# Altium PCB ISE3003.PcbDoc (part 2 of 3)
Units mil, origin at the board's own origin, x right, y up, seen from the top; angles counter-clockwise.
Board outline 3937.01 x 3937.01 mil, 2 copper layers (Top Layer, Bottom Layer), stack 62 mil thick; 230 components, 119 nets, 522 pads, 174 vias.
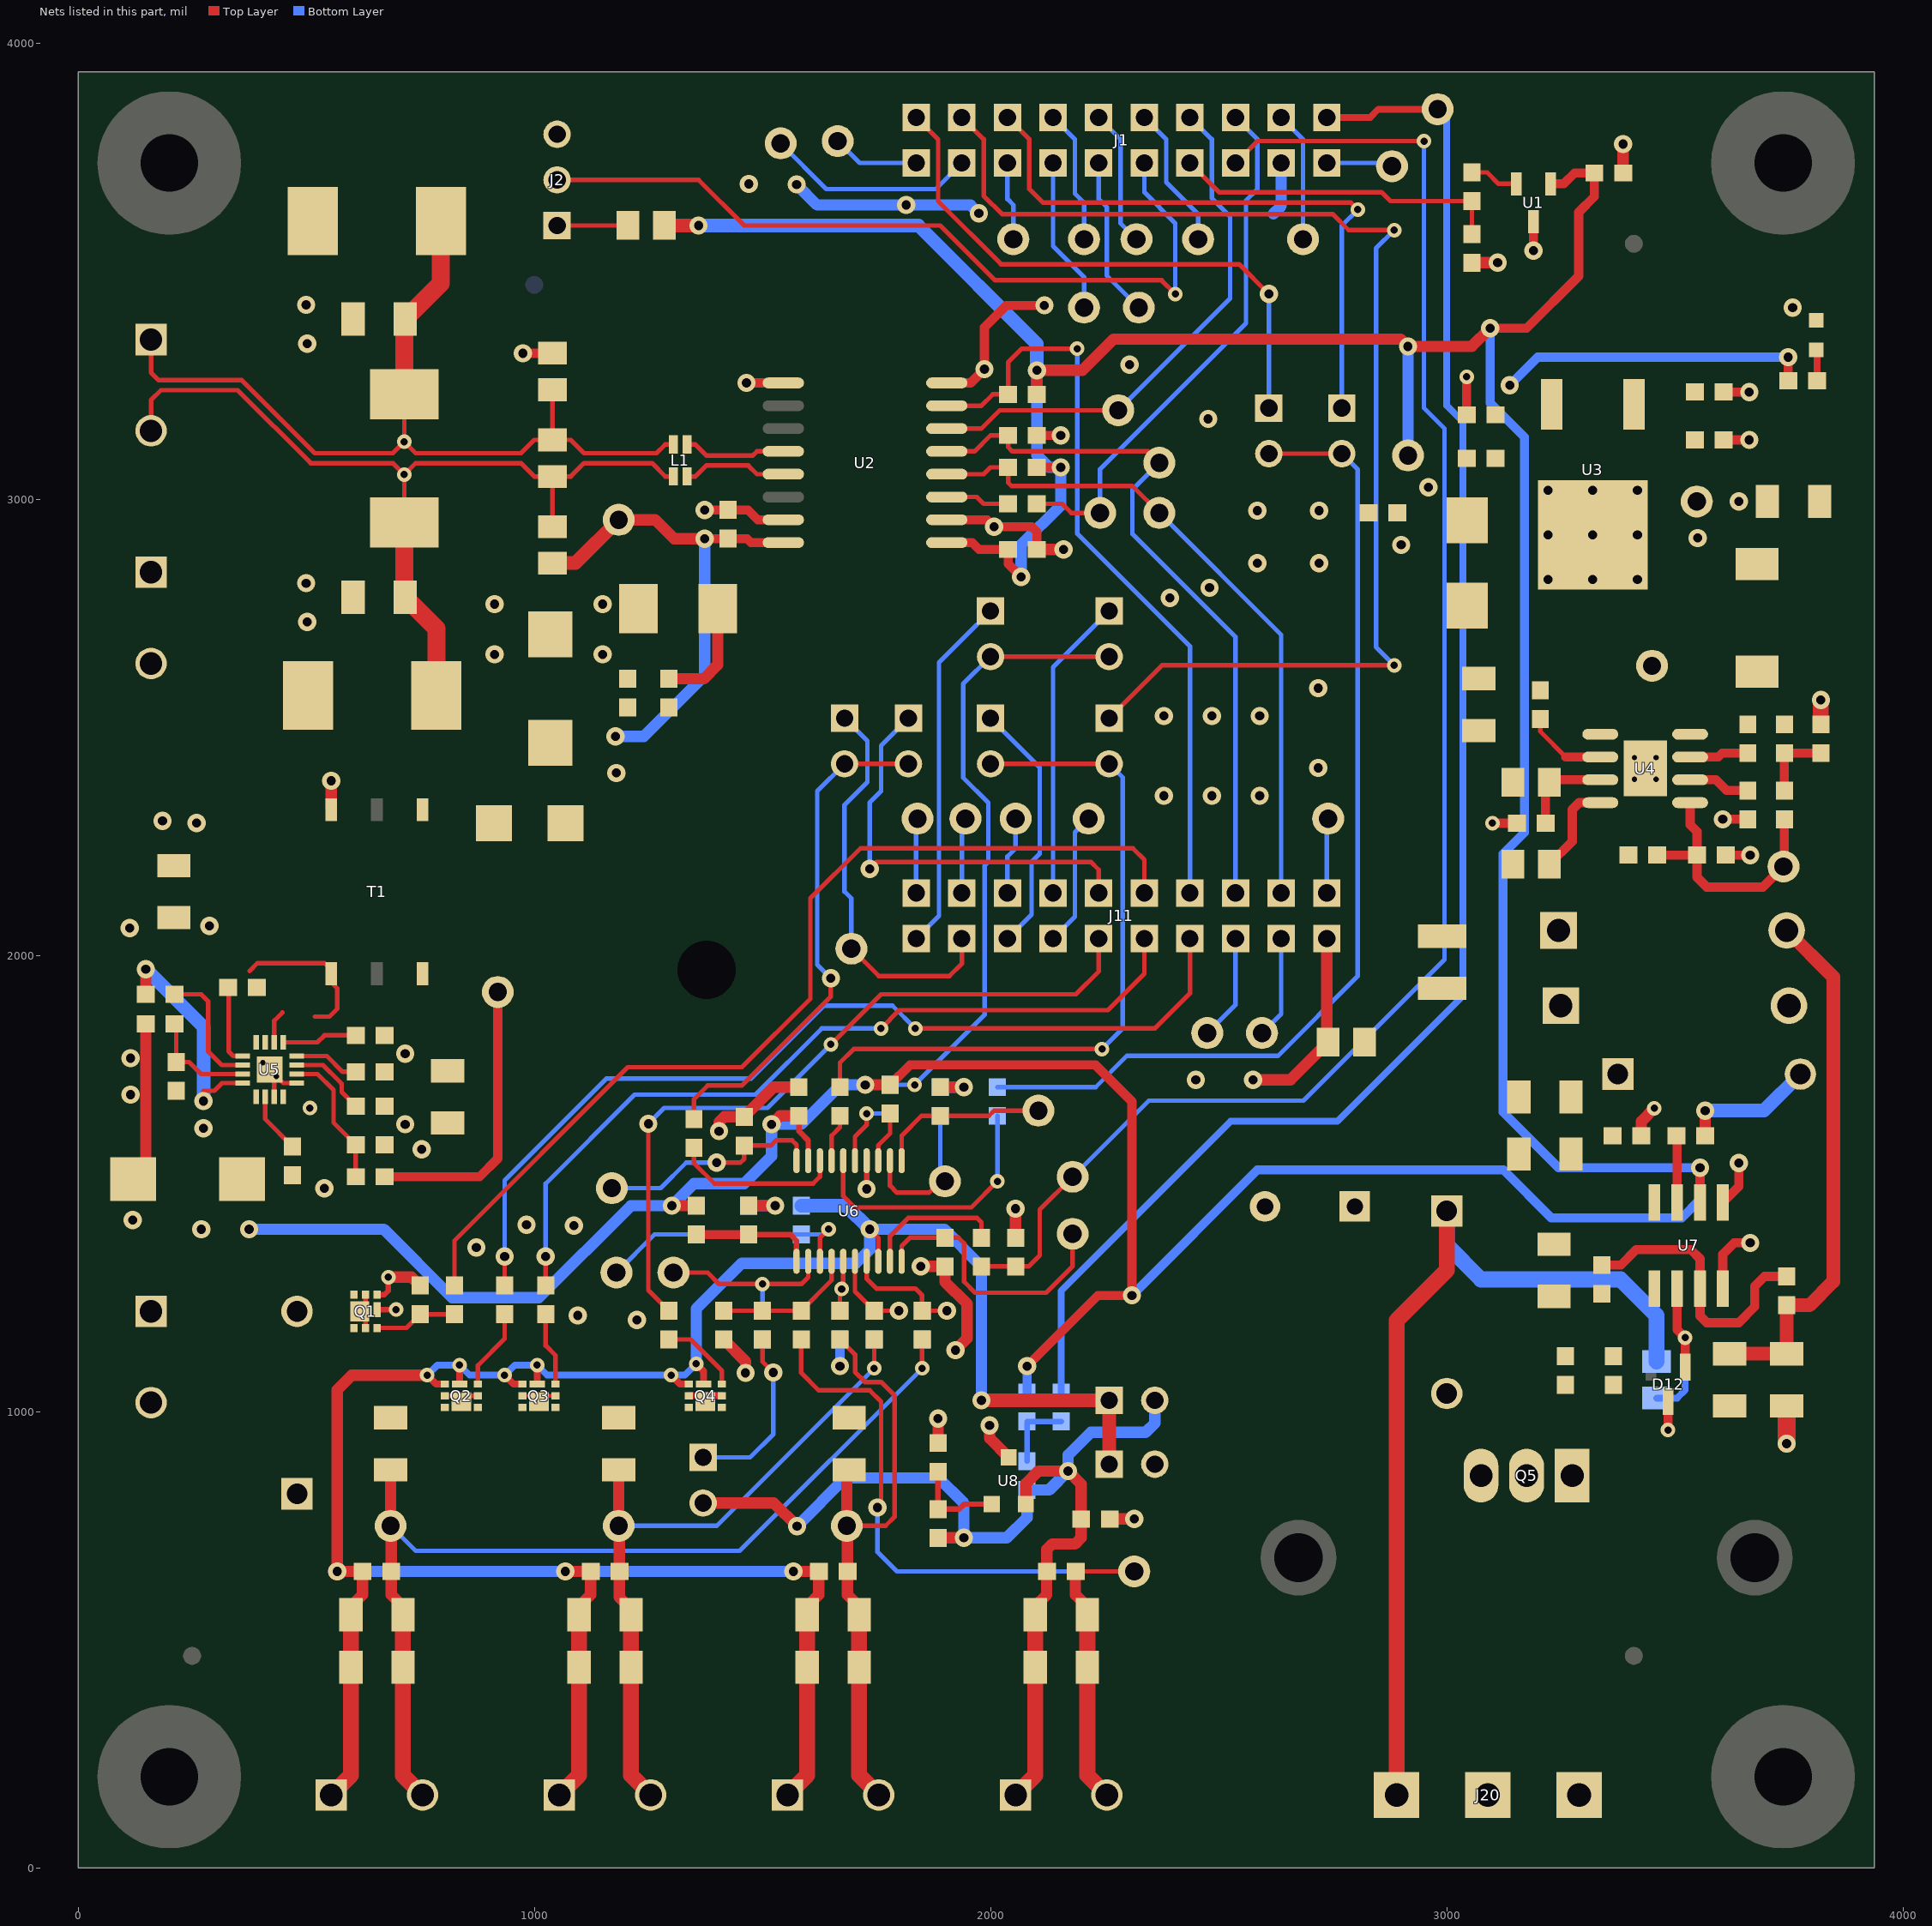
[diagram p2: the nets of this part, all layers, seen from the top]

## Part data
C1 C2 C10 C11 C15 C16 C20 C22 C23 C26 C30 C32 C34 C37 C38: "CAP, CERM, 0.1uF, 25V, +/-5%, X7R, 0603"
C3 C12 C21: "CAP, CERM, 1000pF, 1000V, +/-10%, X7R, 1206"
C4 C7: "CAP, CERM, 1uF, 16V, +/-10%, X7R, 0603"
C5 C8 C29: "CAP, CERM, 0.1uF, 50V, +/-10%, X7R, 0603"
C6: "CAP, TA, 4.7uF, 35V, +/-10%, 1.9 ohm, SMD"
C9: "CAP, CERM, 22uF, 16V, +/-10%, X5R, 1206"
C13 C31: "CAP, TA, 47uF, 35V, +/-10%, 0.3 ohm, SMD"
C14: "CAP, CERM, 1uF, 100V, +/-10%, X7R, 1206"
C17 C27 C33 C35 C36 C43 C44: "CAP, CERM, 0.01uF, 25V, +/-5%, C0G/NP0, 0603"
C18: "CAP, CERM, 3300pF, 50V, +/-10%, X7R, 0603"
C19: "CAP, CERM, 1uF, 25V, +/-10%, X5R, 0603"
C24: "CAP, CERM, 0.1uF, 100V, +/-10%, X7R, 0805"
C25: "CAP, CERM, 22uF, 16V, +/-20%, X5R, 1206"
C28: "CAP, AL, 100uF, 100V, +/-20%, 0.12 ohm, TH"
C39 C40 C41 C42: "CAP, CERM, 100pF, 25V, +/-10%, X7R, 0603"
D1 D3 D5: "Diode, TVS 15V 1500W BIDIR 5% SMC"
D2: "LED SmartLED Green 570NM"
D4: "Diode, Zener, 5.1V, 5W, SMB"
D6: "Diode, Schottky, 20V, 1A, SMA"
D7: "Diode, Zener, 39V, 1W, DO41"
D8: "Diode, Zener, 16V, 1W, DO41"
D9 D10 D11: "Diode, P-N, 1000V, 1A, TH"
D12: "Diode, Switching, 200V, 0.2A, SOT-23"
FB1: library part MMZ1608B102C, "FERRITE CHIP 1000 OHM 300MA 0603"
FID1 FID2 FID3 FID4 FID5 FID6: "Fiducial mark.  There is nothing to buy or mount."
H1 H2 H3 H4: "Machine Screw, Round, #4-40 x 1/4, Nylon, Philips panhead"
H5 H6 H8 H9: "Standoff, Hex, 0.5\"L #4-40 Nylon"
H7: library part "MH 3_0.5MM", "Mountin hole, NPTH Drill 3.2mm"
HS1: "Heatsink, TO-220, Vertical-mount, 5*C/W"
J1 J11: "Header, Male 2x10-pin, 100mil spacing"
J2: "Header, Male 3-pin, 100mil spacing,"
J3 J6 J12 J16 J17 J18 J19: "TERMINAL BLOCK 5.08MM VERT 2POS, TH"
J4 J5 J7 J8 J9 J10 J13 J14 J15 J21 J22: "Header, Male 2-pin, 100mil spacing,"
J20: "Terminal Block, 3-pin, 15-A, 5.1mm"
L1: library part IND_ACM2012_SERIES, "Inductor, Common Mode Filter SMD"
L2: library part IND_SRR7032-221M, "Inductor, 220uH .30A SMD"
L3: library part IND_B82422H1332K, "Inductor, Chip, 3.3uH 770MA 1210 10%"
L4: "1.5A Ferrite Bead, 330 ohm @ 100MHz, SMD"
LBL1: library part THT-14-423-10, "Thermal Transfer Printable Labels, 0.650\" W x 0.200\" H - 10,000 per roll"
Logo1: library part TI_Logo, "Texas Instrument Corporate Signature"
Q1 Q2 Q3 Q4: "MOSFET, N-CH, 30V, 22A, SON 2X2 MM"
Q5: "MOSFET, N-CH, 60V, 50A, TO-220AB"
R1 R33 R41 R68: "RES, 100 ohm, 1%, 0.1W, 0603"
R2: "RES, 1.00k ohm, 1%, 0.125W, 0805"
R3 R10: "RES, 470 ohm, 1%, 0.125W, 0805"
R4 R37 R38 R39 R40: "RES, 300 ohm, 5%, 0.1W, 0603"
R5 R6 R8: "RES, 10k ohm, 5%, 0.1W, 0603"
R7: "RES, 120 ohm, 5%, 0.125W, 0805"
R9: "RES, 10.0 ohm, 1%, 0.1W, 0603"
R11: "RES, 200 ohm, 1%, 0.1W, 0603"
R12: "RES, 63.4k ohm, 1%, 0.1W, 0603"
R13: "RES, 121k ohm, 0.1%, 0.125W, 0805"
R14 R22 R28: "RES, 10.0k ohm, 1%, 0.1W, 0603"
R15: "RES, 1.00k ohm, 1%, 0.1W, 0603"
R16: "RES, 9.76k ohm, 1%, 0.1W, 0603"
R17: "RES, 53.6k ohm, 0.1%, 0.125W, 0805"
R18 R31: "RES, 100k ohm, 1%, 0.1W, 0603"
R19: "RES, 21.5k ohm, 1%, 0.1W, 0603"
R20 R52: "RES, 30k ohm, 5%, 0.1W, 0603"
R21: "RES, 280k ohm, 1%, 0.1W, 0603"
R23 R27 R61 R62: "RES, 10 ohm, 5%, 0.1W, 0603"
R24 R26 R32 R63 R64 R65 R67 R71: "RES, 0 ohm, 5%, 0.1W, 0603"
R25 R29 R34: "RES, 10.0k ohm, 1%, 0.25W, 1206"
R30: "RES, 43.2k ohm, 1%, 0.1W, 0603"
R35: "RES, 1.00Meg ohm, 1%, 0.1W, 0603"
R36 R51: "RES, 10k ohm, 0.01%, 0.063W, 0603"
R42 R43 R44 R70: "RES, 1.0k ohm, 5%, 0.1W, 0603"
R45 R46: "RES, 1.00k ohm, 1%, 0.25W, 1206"
R47: "RES, 510 ohm, 0.1%, 0.1W, 0603"
R48 R49 R50 R53 R54 R55 R56 R57 R58 R59 R60: "RES, 22 ohm, 5%, 0.25W, 1206"
R66: "RES, 47k ohm, 5%, 0.125W, 0805"
R69: "RES, 470 ohm, 5%, 0.1W, 0603"
T1: library part "TRNSFMR 760390015", "Transformer 475uH SMD"
TP1 TP2 TP3 TP4 TP5 TP6 TP7 TP8 TP9 TP10 TP11 TP12 TP13 TP14 TP15 TP16 TP17 TP18 TP19 TP20 TP21 TP22 TP23 TP24 TP25 TP26 TP27 TP28 TP29 TP30 TP31 TP32 TP33 TP34 TP35 TP36 TP37 TP38 TP39 TP40: "Test Point, O.040 Hole"
U1: "2.7V, 15.6mV/°C, Temperature Sensor, 3-pin SOT-23"
U2: "IC, ISOLATED RS-485 PROFIBUS TRANSCEIVER"
U3: "IC, 300-mA 40-V LOW-DROPOUT REGULATOR WITH 25-uA QUIESCENT CURRENT"
U4: "100V, 600mA Constant On-Time Synchronous Buck Regulator, DDA0008B"
U5: "IC, DC-DC Converter"
U6: "ZerØ-Drift Programmable Gain Amplifier with MUX"
U7: "IC, Dual Differential Comparators, 2-36 Vin"
U8: "IC, Micropower Shunt Voltage Reference 100 ppm/°C, 45µA-12mA,  Adjustable"
ZZ1: library part AssemblyNoteLabel
ZZ2 ZZ3 ZZ4: library part AssemblyNote

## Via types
v1: diameter 40, hole 20, Top Layer to Bottom Layer, tented both sides, 134 vias
v2: diameter 32, hole 16, Top Layer to Bottom Layer, tented both sides, 34 vias
v3: diameter 26, hole 12, Top Layer to Bottom Layer, tented both sides, 6 vias

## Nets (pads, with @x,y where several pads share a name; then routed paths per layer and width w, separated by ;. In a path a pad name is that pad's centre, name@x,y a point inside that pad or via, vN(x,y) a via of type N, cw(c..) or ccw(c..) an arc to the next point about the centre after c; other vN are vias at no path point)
3.3_REF: J1.1 R67.1 TP1.1 | length 3588.3
  Top Layer w15: J1.1@2737.01,3837.01 2832.01,3837.01 2850,3855 TP1.1@2980,3855
  Bottom Layer w15: R67.1@2155,1041.5 2155,1265 2526.5,1636.5 2760.5,1636.5 3035,1911 3035,3170 3000,3205 3000,3835 TP1.1@2980,3855
12V: C5.1 C7.1 C9.1 C18.1 D9.2 D11.1 J12.2 L2.2 R16.2 R28.2 TP15.1 U3.1 | length 403.6
  Top Layer w20: R16.2@3611.5,2220 v1(3665,2220)
  Top Layer w25: R28.2@3566.5,1605 v1(3566.5,1660)
  Top Layer w35: C18.1@3820,2506.5 v1(3820,2560)
  Bottom Layer w30: v1(3566.5,1660) 3695,1660 D9.2@3775,1740
  other v1: 3550,2915 3640,2995
16V_C: C29.1 D8.1 D9.1 R25.1 R29.1 R34.1 U7.8
39V: C24.1 C28.1 D7.1 D10.1 J20.1 L3.1 R25.2 R29.2 R66.2 | length 2027.4
  Top Layer w35: J20.1@2890,158 J20.1@2890,160 2890,1200 3000,1310 D10.1@3000,1440
  Bottom Layer w35: D10.1@3000,1440 3000,1365 3075,1290 3381,1290 3460,1211 R66.2@3460,1110
\CS: J21.2 J22.2 R27.2 | length 1124
  Top Layer w10: R27.2@1350,1641.5 1350,1685 1380,1715 1455,1715 1650,1910 v1(1650,1950) ; J22.2@1680,2420 J21.2@1820,2420
  Bottom Layer w10: v1(1650,1950) 1620,1980 1620,2360 J22.2@1680,2420
\CS_M: J11.11 J21.1 | length 931.5
  Top Layer w10: v1(1735,2190) 1750,2205 2220,2205 2237.01,2187.99 J11.11@2237.01,2137.01
  Bottom Layer w10: v1(1735,2190) 1735,2335 1760,2360 1760,2460 J21.1@1820,2520
\CS_T: J11.18 J22.1 TP26.1 | length 885.7
  Top Layer w10: TP26.1@1695,2015 1755,1955 1910,1955 1937.01,1982.01 J11.18@1937.01,2037.01
  Bottom Layer w10: J22.1@1680,2520 1730,2470 1730,2380 1680,2330 1680,2140 1695,2125 TP26.1@1695,2015
AVDD: C32.2 L4.1 U6.1 | length 270.8
  Top Layer w12: C32.2@1470,1388.5 1561.5,1388.5 1574.84,1375.16 U6.1@1574.84,1329.76
  Top Layer w20: L4.1@1355,1388.5 C32.2@1470,1388.5
B_G: J11.12 R40.1 | length 1625.5
  Top Layer w10: v1(1250,1631) 1250,1266.5 R40.1@1295,1221.5 ; v2(1650,1805) 1760,1915 2187.01,1915 2237.01,1965 J11.12@2237.01,2037.01
  Bottom Layer w10: v1(1250,1631) 1285,1666 1511,1666 v2(1650,1805)
B_IP: C41.1 J18.2 R50.1 R55.2 R59.2 R70.1 TP33.1 | length 1334.9
  Top Layer w10: R70.1@1670,1158.5 1703,1125.5 1703,1087 1725,1065 1760,1065 1790,1035 1790,770 1770,750 TP33.1@1685,750
  Top Layer w25: R50.1@1680,882.91 1685,877.91 TP33.1@1685,750 ; TP33.1@1686.5,748.5 C41.1@1686.5,650 1686.5,598.5 1712.09,572.91 R55.2@1712.09,555
  Top Layer w35: R55.2@1712.09,555 R59.2@1712.09,440 1712.09,202.91 J18.2@1755,160
  Bottom Layer w10: TP33.1@1677.2,757.8 TP33.1@1685,750
C5V: C10.2 C13.1 C15.1 D6.1 R10.2 R11.2 TP18.1 U2.16 | length 1116.7
  Top Layer w20: v1(1373.5,2913.5) C10.2@1425,2913.5 1466.5,2913.5 1475,2905 U2.16@1545.87,2905
  Top Layer w25: TP18.1@1185,2955 1265,2955 1306.5,2913.5 v1(1373.5,2913.5)
  Top Layer w30: R10.2@1040,2860 1090,2860 TP18.1@1185,2955
  Bottom Layer w25: v1(1178,2480) 1240,2480 1373.5,2613.5 v1(1373.5,2913.5)
  other v1: 1180,2400
EGND: C3.2 C12.1 D1.1 D5.2 J6.2
  other v1: 502.5,2731 500,2816 502.5,3341 500,3426
FSD: J11.9 R37.1 | length 2179
  Top Layer w10: R37.1@825,1276.5 825,1375 1205,1755 1455.06,1755 1605.06,1905 1605.06,2125.06 1715,2235 2312.01,2235 2337.01,2210 J11.9@2337.01,2137.01
GND: C1.2 C2.1 C4.2 C5.2 C6.2 C7.2 C8.2 C9.2 C11.1 C14.1 C16.2 C19.2 C21.2 C23.1 C24.2 C25.2 C26.1 C27.2 C28.2 C29.2 C30.2 C31.2 C32.1 C33.2 C34.2 C35.2 C36.2 C38.1 C43.2 C44.2 D2.1 D8.2 D12.3 J1.4 J2.3 J11.2 J15.2 J20.2 Q1.4 Q1.7 Q5.3 R6.1 R14.1 R15.1 R19.1 R21.1 R24.1 R26.1 R30.1 R32.1 R45.1 R46.1 R51.1 R63.1 R64.1 R65.1 U1.3 U2.2 U2.8 U3.2 U4.1 U4.9 U5.3 U5.4 U5.5 U5.17 U6.14 U7.4 U7.5 U8.3 | length 4458.4
  Top Layer w10: U5.17@420.05,1750.15 U5.17@429.85,1740.35 ; U5.3@429.85,1680.15 U5.3@429.85,1690.55 U5.17@429.85,1740.35 ; U5.5@479.5,1720.5 449.7,1720.5 U5.17@429.85,1740.35
  Top Layer w12: Q1.7@655.59,1223.78 v2(697.2,1223.78) ; Q1.4@655.59,1256.32 671.32,1256.32 680,1265 v2(680,1295) ; v1(1728.39,1488.39) U6.14@1728.39,1550.24
  Top Layer w20: U2.2@1904.13,2955 1993,2955 v1(2008,2940) 2090,2940 2101.5,2928.5 C11.1@2101.5,2890 ; U2.8@1904.13,3255 1956.64,3255 v1(1986.64,3285) 1986.64,3376.64 2035,3425 v1(2118,3425) ; R6.1@2101.5,3140 v1(2154,3140) ; C4.2@3043.5,3185 v2(3043.5,3268.5) ; v2(3100,2290) R14.1@3148.5,2290 ; v1(3190,3545) U1.3@3190,3608.66 ; v2(3485,960) D12.3@3485,1022.6 ; U7.4@3605,1270 3605,1345 3630,1370 v1(3665,1370) ; U7.5@3605,1459 3640,1494 v1(3640,1545) ; v1(3605,2298.5) C19.2@3660,2298.5 ; C7.2@3606.5,3130 v1(3663,3130) ; C5.2@3606.5,3235 v1(3663,3235)
  Top Layer w25: C31.2@120.91,1510 148.5,1537.6 R19.1@148.5,1850 ; v2(680,1295) 730.45,1295 748.96,1276.5 C34.2@750,1276.5 ; v1(1405,1615) 1405,1635 1416.5,1646.5 R26.1@1460,1646.5 1525,1711.5 C26.1@1580,1711.5 ; C35.2@1415,1158.5 1463,1110.5 v1(1463,1085) ; C32.1@1470,1451.5 v1(1528,1451.5) ; v1(1847.16,1318.5) R32.1@1900,1318.5 1900,1285 1948.5,1236.5 1948.5,1160.5 v1(1923,1135) ; R51.1@1885,931.5 v1(1885,985) ; R24.1@1890,1711.5 v1(1941.5,1711.5) ; v1(1998,970) 1998,942 U8.3@2040,900 ; C33.2@2055,1381.5 v1(2055,1445) ; C11.1@2101.5,2890 v1(2160,2890) ; C38.1@2261.5,765 v1(2315,765) ; v1(2575.5,1727.5) 2657.5,1727.5 C24.2@2740,1810 2737.01,1812.99 J11.2@2737.01,2037.01 ; C2.1@3055,3518.5 v1(3111.5,3518.5) ; C1.2@3386.5,3715 v1(3386.5,3778.5) ; C29.2@3426.5,1605 3426.5,1636.5 v2(3455,1665)
  Top Layer w40: v1(3745,930) R46.1@3745,1012.91
  Bottom Layer w20: v1(1670,1100) C36.2@1670,1158.5
  Bottom Layer w25: R64.1@1470,1451.5 v1(1528,1451.5) ; v1(1575,3690) 1620,3645 v1(1815,3645) 1956,3645 v1(1974.5,3626.5) ; R63.1@1890,1711.5 v1(1941.5,1711.5) ; 2620,3626 2637.01,3643.01 J1.4@2637.01,3737.01
  other v1: 1225,1201 1095,1211 873,1360 1087,1408 983,1410 120,1420 539.95,1489.85 753,1575 717,1630 115,1695 2450,1727.5 115,1775 717,1785 113,2060 288,2065 2380,2350 2485,2350 2590,2350 2718.01,2411 2380,2525 2485,2525 2590,2525 2718.01,2586 2393,2784 2480,2806 3222,2823.89 3320,2823.89 3418,2823.89 2585,2860 2720,2860 3222,2921.89 3320,2921.89 3418,2921.89 2585,2975 2720,2975 3222,3019.89 3320,3019.89 3418,3019.89 2477,3176 2305,3295 3758,3420 1470,3691
  other v2: 507.95,1665.85
  other v3: 434.95,1734.85 404.95,1764.85 3411.38,2386.38 3458.62,2386.38 3411.38,2433.62 3458.62,2433.62
N_IP: C42.1 J19.2 R42.1 R56.2 R60.2 TP34.1 | length 1842.5
  Top Layer w10: R42.1@1585,1158.5 1585,1085 1623,1047 1735,1047 1760,1022 1760,798 v1(1752,790) ; C42.1@2186.5,650 TP34.1@2315,650
  Top Layer w25: C42.1@2185.99,650 2185.99,598.5 2211.58,572.91 R56.2@2211.58,555
  Top Layer w35: R56.2@2212.09,562.91 R56.2@2212.09,555 R60.2@2212.09,440 2212.09,202.91 J19.2@2255,160
  Bottom Layer w10: v1(1752,790) 1752,693 1795,650 TP34.1@2315,650
NetC4_1: C4.1 FB1.1 R4.2 U3.3 | length 687.5
  Top Layer w20: R4.2@3748.5,3260 v1(3748.5,3311.5)
  Bottom Layer w20: v1(3138,3250) 3199.5,3311.5 v1(3748.5,3311.5)
NetC14_2: C14.2 C16.1 L3.2 R13.2 R17.2 U4.2 | length 182.3
  Top Layer w10: C16.1@3205,2518.5 3205,2491 3261,2435
  Top Layer w20: 3261,2435 U4.2@3336.57,2435
NetC17_1: C17.1 U4.7 | length 130.1
  Top Layer w20: U4.7@3533.43,2435 3595,2435 3603.5,2443.5 C17.1@3660,2443.5
NetC17_2: C17.2 L2.1 R12.1 TP19.1 U4.8
NetC18_2: C18.2 C20.2 R12.2 | length 162
  Top Layer w20: C20.2@3740,2361.5 R12.2@3740,2443.5 C18.2@3820,2443.5
NetC19_1: C19.1 U4.6 | length 136.3
  Top Layer w20: U4.6@3533.43,2385 3590,2385 3613.5,2361.5 C19.1@3660,2361.5
NetC20_1: C20.1 R15.2 R16.1 TP25.1 U4.5 | length 578.1
  Top Layer w20: R15.2@3461.5,2220 R16.1@3548.5,2220 ; U4.5@3533.43,2335 3533.43,2286.57 3548.5,2271.5 R16.1@3548.5,2220 ; C20.1@3740,2298.5 3740,2197 TP25.1@3738,2195 3693,2150 3570,2150 3548.5,2171.5 R16.1@3548.5,2220
NetC22_1: C22.1 T1.1 U5.10 U5.11 U5.12 | length 411.6
  Top Layer w10: 376,1966 393,1983 540,1983 555,1968 T1.1@555,1960 555,1940.95 568,1927.95 568,1882.9 551.1,1866 519.15,1866 ; U5.10@429.85,1809.55 429.85,1856.85 448,1875
NetC22_2: C22.2 U5.13 | length 175.4
  Top Layer w10: C22.2@328.5,1930 330,1928.5 330,1790 340.4,1779.6 U5.13@360.5,1779.6
NetC23_2: C23.2 U5.9 | length 165.4
  Top Layer w10: U5.9@449.55,1809.55 524.55,1809.55 540,1825 C23.2@608.5,1825
NetC25_1: C25.1 R31.1 T1.3 TP27.1 | length 630.1
  Top Layer w20: R31.1@671.5,1515 880,1515 920,1555 TP27.1@920,1920
NetC27_1: C27.1 U5.7 | length 176.9
  Top Layer w10: U5.7@479.5,1759.9 536.83,1759.9 571.73,1725 578,1718.72 578,1700.5 C27.1@608.5,1670
NetC34_1: C34.1 Q1.3 R37.2 | length 181.8
  Top Layer w10: Q1.3@655.59,1183.68 720.18,1183.68 C34.1@750,1213.5 R37.2@825,1213.5
NetC35_1: C35.1 R41.1 R42.2 U6.4 | length 305.9
  Top Layer w10: C35.1@1415,1221.5 R41.1@1500,1221.5 R42.2@1585,1221.5 1651.61,1288.11 U6.4@1651.61,1329.76
NetC36_1: C36.1 R70.2 U6.5 | length 160.5
  Top Layer w10: R70.2@1670,1221.5 1670,1266 1677.2,1273.2 U6.5@1677.2,1329.76
  Bottom Layer w10: C36.1@1670,1221.5 1670,1265.48 v2(1673.7,1269.18)
NetC37_1: C37.1 R34.2 R35.2 R47.1 U7.1
NetC37_2: C37.2 Q5.1 R47.2
NetC43_1: C43.1 R44.2 U6.7 | length 317
  Top Layer w10: U6.7@1728.39,1329.76 1728.39,1291.61 1750,1270 1835,1270 1850,1255 R44.2@1850,1221.5 v1(1904.3,1221.5)
  Bottom Layer w10: C43.1@1850,1221.5 v1(1904.3,1221.5)
NetC44_1: C44.1 R43.2 U6.6 | length 234.3
  Top Layer w10: U6.6@1702.8,1329.76 1702.8,1263.7 R43.2@1745,1221.5 v1(1799.3,1221.5)
  Bottom Layer w10: C44.1@1745,1221.5 v1(1799.3,1221.5)
NetD2_2: D2.2 R4.1 | length 66
  Top Layer w15: R4.1@3811.5,3260 D2.2@3811.5,3326.02
NetD4_1: D4.1 R11.1 | length 242.6
  Top Layer w25: R11.1@1295,2606.5 1371.5,2606.5 1402.01,2637.01 D4.1@1402.01,2760
NetD6_2: D6.2 T1.4
NetD7_2: D7.2 R36.2 R45.2 R46.2 | length 1166.7
  Top Layer w30: R45.2@3620,1127.09 R46.2@3745,1127.09 R36.2@3745,1233.5 3795,1233.5 3847.01,1285.51 3847.01,1952.99 D7.2@3745,2055
NetD10_2: D10.2 J20.3 Q5.2
NetD11_2: D11.2 J12.1 Q1.1 Q1.2 Q1.5 Q1.6 Q1.8 | length 72.6
  Top Layer w10: Q1.2@630,1183.68 Q1.5@630,1256.32
NetD12_1: D12.1 R66.1 U7.2 | length 364.6
  Top Layer w20: U7.2@3505,1270 3505,1180 v2(3522.4,1162.6) D12.1@3522.4,1097.4
  Bottom Layer w15: R66.1@3460,1030 3505,1030 3522.4,1047.4 v2(3522.4,1162.6)
NetJ1_2: J1.2 TP4.1 | length 145.9
  Bottom Layer w10: J1.2@2737.01,3737.01 2872.99,3737.01 TP4.1@2880,3730
NetJ1_3: J1.3 TP9.1 | length 286.9
  Bottom Layer w10: J1.3@2637.01,3837.01 2685,3789.02 TP9.1@2685,3570
NetJ1_9: J1.9 TP8.1 | length 315.9
  Bottom Layer w10: J1.9@2337.01,3837.01 2385,3789.02 2385,3695 2455,3625 TP8.1@2455,3570
NetJ1_11: J1.11 TP7.1 | length 301.4
  Bottom Layer w10: J1.11@2237.01,3837.01 2285,3789.02 2285,3605 TP7.1@2320,3570
NetJ1_12: J1.12 TP11.1 | length 353.5
  Bottom Layer w10: J1.12@2237.01,3737.01 2237.01,3657.99 2255,3640 2255,3490 TP11.1@2325,3420
NetJ1_13: J1.13 TP6.1 | length 295.2
  Bottom Layer w10: J1.13@2137.01,3837.01 2185,3789.02 2185,3670 2205,3650 TP6.1@2205,3570
NetJ1_14: J1.14 TP10.1 | length 345.2
  Bottom Layer w10: J1.14@2137.01,3737.01 2137.01,3555 2205,3487.01 TP10.1@2205,3420
NetJ1_16: J1.16 TP5.1 | length 172.4
  Bottom Layer w10: J1.16@2037.01,3737.01 2037.01,3657.99 2050,3645 TP5.1@2050,3570
NetJ1_18: J1.18 TP3.1 | length 462
  Bottom Layer w10: TP3.1@1540,3780 1640,3680 1880,3680 J1.18@1937.01,3737.01
NetJ1_20: J1.20 TP2.1 | length 191.9
  Bottom Layer w10: TP2.1@1665,3785 1712.99,3737.01 J1.20@1837.01,3737.01
NetJ2_1: J2.1 R2.1 | length 155
  Top Layer w10: J2.1@1050,3600 R2.1@1205,3600
NetJ11_1: J11.1 TP24.1 | length 164.2
  Bottom Layer w10: J11.1@2737.01,2137.01 2737.01,2297.01 TP24.1@2740,2300
NetJ11_4: J11.4 TP29.1 | length 224.4
  Bottom Layer w10: TP29.1@2595,1830 2637.01,1872.01 J11.4@2637.01,2037.01
NetJ11_6: J11.6 TP28.1 | length 232.7
  Bottom Layer w10: TP28.1@2475,1830 2537.01,1892.01 J11.6@2537.01,2037.01
NetJ11_14: J11.14 TP23.1 | length 295.3
  Bottom Layer w10: J11.14@2137.01,2037.01 2185,2085 2185,2270 TP23.1@2215,2300
NetJ11_15: J11.15 TP22.1 | length 170.4
  Bottom Layer w10: J11.15@2037.01,2137.01 2037.01,2217.01 2055,2235 TP22.1@2055,2300
NetJ11_17: J11.17 TP21.1 | length 166.3
  Bottom Layer w10: J11.17@1937.01,2137.01 1937.01,2292.01 TP21.1@1945,2300
NetJ11_19: J11.19 TP20.1 | length 164.2
  Bottom Layer w10: J11.19@1837.01,2137.01 1837.01,2297.01 TP20.1@1840,2300
NetJ14_1: J14.1 R41.2 | length 392.6
  Top Layer w10: R41.2@1500,1158.5 1500,1110 v1(1524,1086)
  Bottom Layer w10: J14.1@1370,900 1473,900 1524,951 v1(1524,1086)
NetL1_1: L1.1 U2.13 | length 228.7
  Top Layer w10: L1.1@1335,3050 1353,3050 1377,3074 1469,3074 1488,3055 U2.13@1545.87,3055
NetL1_2: L1.2 U2.12 | length 224.5
  Top Layer w10: L1.2@1335,3120 1353,3120 1377,3096 1479,3096 1488,3105 U2.12@1545.87,3105
NetQ2_1: Q2.1 Q2.2 Q2.5 Q2.6 Q2.8 R48.2 | length 72.6
  Top Layer w10: Q2.5@803.68,1035 Q2.2@876.32,1035
NetQ2_3: Q2.3 R38.2 | length 177.2
  Top Layer w10: Q2.3@876.32,1060.59 876.32,1101.32 935,1160 R38.2@935,1213.5
NetQ3_1: Q3.1 Q3.2 Q3.5 Q3.6 Q3.8 R49.2 | length 68.3
  Top Layer w8: Q3.5@978,1035 Q3.2@1046.32,1035
NetQ3_3: Q3.3 R39.2 | length 161.7
  Top Layer w10: R39.2@1025,1213.5 1025,1145 1046.32,1123.68 Q3.3@1046.32,1060.59
NetQ4_1: Q4.1 Q4.2 Q4.5 Q4.6 Q4.8 R50.2 | length 72.6
  Top Layer w15: Q4.5@1338.68,1035 Q4.2@1411.32,1035
NetQ4_3: Q4.3 R40.2 | length 173.9
  Top Layer w10: R40.2@1295,1158.5 1342.51,1158.5 1411.32,1089.69 Q4.3@1411.32,1060.59
NetR1_1: R1.1 U1.2 | length 108
  Top Layer w10: R1.1@3055,3716.5 3088.5,3716.5 3113.66,3691.34 U1.2@3152.6,3691.34
NetR9_2: R9.2 U2.3 | length 140.6
  Top Layer w10: U2.3@1904.13,3005 1970,3005 1985,2990 R9.2@2038.5,2990
NetR13_1: R13.1 R14.2 U4.3 | length 205.1
  Top Layer w20: R14.2@3216.5,2290 3216.5,2371.5 R13.1@3225,2380 ; R13.1@3225,2385 U4.3@3336.57,2385
NetR17_1: R17.1 U4.4 | length 208.5
  Top Layer w20: R17.1@3225,2200 3275,2250 3275,2320 3290,2335 U4.4@3336.57,2335
NetR18_1: R18.1 U5.14 | length 277.7
  Top Layer w10: R18.1@211.5,1915 270,1915 285,1900 285,1790 315.1,1759.9 U5.14@360.5,1759.9
NetR19_2: R19.2 R20.1 U5.15 | length 231.3
  Top Layer w10: R19.2@211.5,1840 215,1836.5 R20.1@215,1766.5 243.5,1766.5 269.8,1740.2 U5.15@360.5,1740.2
NetR21_2: R21.2 U5.8 | length 143.3
  Top Layer w10: U5.8@479.5,1779.6 545.4,1779.6 580,1745 R21.2@608.5,1745
NetR22_2: R22.2 U6.13 | length 114
  Top Layer w10: U6.13@1753.98,1550.24 1753.98,1583.98 1780,1610 R22.2@1780,1653.5
NetR23_1: R23.1 U6.17 | length 105.9
  Top Layer w10: U6.17@1651.61,1550.24 1651.61,1605 1670,1623.39 R23.1@1670,1648.5
NetR24_2: R24.2 TP39.1 U6.11 | length 367.5
  Top Layer w10: U6.11@1805.16,1550.24 1805.16,1605.16 1848.5,1648.5 R24.2@1880,1648.5 ; R24.2@1890,1648.5 1996.5,1648.5 2008,1660 TP39.1@2105,1660
NetR26_2: R26.2 TP37.1 U6.20 | length 504.6
  Top Layer w10: v1(1400,1546) 1452,1546 1460,1554 R26.2@1460,1583.5 1518.5,1583.5 1530,1595 1565,1595 1574.84,1585.16 U6.20@1574.84,1550.24
  Bottom Layer w10: TP37.1@1170,1490 1277,1490 1333,1546 v1(1400,1546)
NetR27_1: R27.1 U6.18 | length 369.6
  Top Layer w10: R27.1@1350,1578.5 1350,1545 1395,1500 1611.02,1500 1626.02,1515 U6.18@1626.02,1550.24
NetR28_1: R28.1 U7.7 | length 144.5
  Top Layer w20: U7.7@3505,1459 R28.1@3505,1603.5
NetR30_2: R30.2 R31.2 U5.6 | length 305.2
  Top Layer w10: U5.6@479.5,1740.2 524.8,1740.2 560,1705 560,1633.5 R30.2@608.5,1585 R31.2@608.5,1515
NetR32_2: R32.2 TP40.1 U6.10 | length 610.1
  Top Layer w10: U6.10@1805.16,1329.76 1805.16,1363.23 1823.43,1381.5 R32.2@1900,1381.5 1929.7,1381.5 1942,1369.2 1942,1285 1966,1261 2122,1261 2180,1319 TP40.1@2180,1390
NetR33_1: R33.1 U6.9 | length 309.6
  Top Layer w10: U6.9@1779.57,1329.76 1779.57,1384.57 1820,1425 1970,1425 1980,1415 R33.1@1980,1381.5
NetR35_1: R35.1 R36.1 U7.3 | length 626.8
  Top Layer w20: R35.1@3340,1321.5 3381.5,1321.5 3415,1355 3535,1355 3555,1335 U7.3@3555,1270 3555,1210 3570,1195 3640,1195 3675,1230 3675,1275 3696.5,1296.5 R36.1@3745,1296.5
NetR51_2: R51.2 R52.1 U8.1 | length 204.1
  Top Layer w12: R51.2@1885,868.5 R52.1@1885,786.5 1931.5,786.5 1942.5,797.5 U8.1@2002.5,797.5
NetR61_1: R61.1 U6.15 | length 165.4
  Top Layer w10: U6.15@1702.8,1550.24 1702.8,1602.8 1728.5,1628.5 v2(1728.5,1653.5)
  Bottom Layer w10: v2(1728.5,1653.5) R61.1@1780,1653.5
NetR62_1: R62.1 U6.16 | length 592.6
  Top Layer w10: U6.16@1677.2,1550.24 1677.2,1472.8 1702,1448 1958,1448 v2(2015,1505)
  Bottom Layer w10: v2(2015,1505) R62.1@2015,1648.5
NetR63_2: R63.2 TP38.1 U6.12 | length 325.5
  Top Layer w10: U6.12@1779.57,1550.24 1779.57,1495.43 1795,1480 1865,1480 TP38.1@1890,1505
  Bottom Layer w10: TP38.1@1890,1505 R63.2@1890,1648.5
NetR64_2: R64.2 R71.1 TP35.1 U6.3 | length 631
  Top Layer w10: U6.3@1626.02,1329.76 1626.02,1381.02 v2(1645,1400)
  Bottom Layer w10: TP35.1@1180,1305 1263.5,1388.5 R64.2@1470,1388.5 1633.5,1388.5 ; R71.1@1585,1388.5 1633.5,1388.5 ; v2(1645,1400) 1633.5,1388.5
NetR65_2: R65.2 TP36.1 U6.2 | length 405.3
  Top Layer w10: TP36.1@1305,1305 1380,1305 1405,1280 v2(1500,1280) 1585.43,1280 1600.43,1295 U6.2@1600.43,1329.76
  Bottom Layer w10: R65.2@1500,1221.5 v2(1500,1280)
NetR67_2: R67.2 R68.2 R69.2 | length 162
  Bottom Layer w12: R69.2@2080,891.5 R68.2@2080,978.5 R67.2@2155,978.5
PGND: C10.1 C13.2 C15.2 C21.1 D4.2 J6.1 R3.1 T1.6 U2.9 U2.15 | length 390.3
  Top Layer w20: v1(975,3320) R3.1@1040,3320 ; v1(1373.5,2976.5) C10.1@1425,2976.5 1468.5,2976.5 1490,2955 U2.15@1545.87,2955 ; v1(1465,3255) U2.9@1545.87,3255
  Top Layer w25: T1.6@555,2319.84 v1(555,2383)
  other v1: 260,2290.5 185,2295 913,2660 1150,2660 913,2770 1150,2770
POT_I: J1.10 J2.2 | length 1773.7
  Top Layer w10: J2.2@1050,3700 1360,3700 1460,3600 1890,3600 2010,3480 2375,3480 v2(2405,3450)
  Bottom Layer w10: J1.10@2337.01,3737.01 2337.01,3672.99 2405,3605 v2(2405,3450)
R: C33.1 J1.6 R33.2 TP30.1 | length 3597.6
  Top Layer w10: R33.2@1980,1318.5 C33.1@2055,1318.5 2083.54,1318.5 2108,1342.96 2108,1443 TP30.1@2180,1515 ; J1.6@2537.01,3737.01 2585,3785 v2(2950,3785)
  Bottom Layer w10: TP30.1@2180,1515 2347,1682 2685.94,1682 2995,1991.06 2995,3155 2950,3200 v2(2950,3785)
R_G: J11.8 R38.1 | length 2063.8
  Top Layer w10: R38.1@935,1276.5 v1(935,1340) ; v2(1835,1840) 2360,1840 2437.01,1917.01 J11.8@2437.01,2037.01
  Bottom Layer w10: v1(935,1340) 935,1507 1158,1730 1475,1730 1635,1890 1785,1890 v2(1835,1840)
R_IP: C39.1 J16.2 R44.1 R48.1 R53.2 R57.2 TP31.1 | length 2158.9
  Top Layer w10: TP31.1@686.5,748.5 TP31.1@687.99,750 ; v2(1850,1095) R44.1@1850,1158.5
  Top Layer w25: TP31.1@685,750 R48.1@685,872.91 ; TP31.1@686.5,748.5 C39.1@686.5,650 686.5,598.5 712.09,572.91 R53.2@712.09,555
  Top Layer w35: R53.2@712.09,555 R57.2@712.09,440 712.09,202.91 J16.2@755,160
  Bottom Layer w10: TP31.1@685,750 740,695 1450,695 v2(1850,1095)
RS485_CHIP_EN: J11.7 R5.1 U2.7 | length 1674
  Top Layer w10: U2.7@1904.13,3205 1980,3205 2005,3230 R5.1@2038.5,3230 2038.5,3300 2068.5,3330 v2(2190,3330)
  Bottom Layer w10: v2(2190,3330) 2190,2925 2437.01,2677.99 J11.7@2437.01,2137.01
RS485_ISO_A: C3.1 D1.2 D3.1 J3.1 L1.3 R3.2 R7.1 | length 1967.4
  Top Layer w10: J3.1@160,3350 160,3277.58 176.58,3261 359,3261 519,3101 690,3101 v2(715,3126) ; D3.1@715,3230.49 v2(715,3126) ; R3.2@1040,3240 R7.1@1040,3130 ; L1.3@1305,3120 1287,3120 1268,3101 1109,3101 1080,3130 R7.1@1040,3130 ; v2(715,3126) 740,3101 971,3101 1000,3130 R7.1@1040,3130
  Top Layer w40: D3.1@715,3230.49 C3.1@715,3392.91 ; C3.1@717.09,3395 795.15,3473.06 D1.2@795.15,3610
RS485_ISO_B: C12.2 D3.2 D5.1 J3.2 L1.4 R7.2 R10.1 | length 1964.5
  Top Layer w10: J3.2@160,3150 160,3217.26 181.74,3239 349.89,3239 509.89,3079 690,3079 v2(715,3054) ; D3.2@715,2949.51 v2(715,3054) ; R10.1@1040,2940 R7.2@1040,3050 ; L1.4@1305,3050 1287,3050 1258,3079 1109,3079 1080,3050 R7.2@1040,3050 ; v2(715,3054) 740,3079 971,3079 1000,3050 R7.2@1040,3050
  Top Layer w40: C12.2@715,2787.09 D3.2@715,2949.51 ; C12.2@717.09,2785 785.49,2716.59 D5.1@785.49,2570
RS485_RX_EN: J11.3 R8.1 TP17.1 U2.4 | length 1476.7
  Top Layer w10: U2.4@1904.13,3055 1985,3055 2000,3070 R8.1@2038.5,3070 2038.5,3036.5 2046,3029 2311,3029 TP17.1@2370,2970
  Bottom Layer w10: TP17.1@2370,2970 2637.01,2702.99 J11.3@2637.01,2137.01
RS485_TX_EN: J11.5 R6.2 TP14.1 U2.5 | length 1581.2
  Top Layer w10: U2.5@1904.13,3105 1965,3105 2000,3140 R6.2@2038.5,3140 2038.5,3114.5 2048,3105 2345,3105 TP14.1@2370,3080
  Bottom Layer w10: TP14.1@2370,3080 2311,3021 2311,2924 2537.01,2697.99 J11.5@2537.01,2137.01
SCLK: J7.2 J8.2 R61.2 | length 1366.5
  Top Layer w10: J7.2@2000,2655 J8.2@2260,2655
  Bottom Layer w10: R61.2@1780,1716.5 v2(1833.5,1716.5) 1987,1869.99 1987,2197 1995,2205 1995,2335 1940,2390 1940,2595 J7.2@2000,2655
SCLK_M: J8.1 J11.13 | length 668.9
  Bottom Layer w10: J11.13@2137.01,2137.01 2137.01,2632.01 J8.1@2260,2755
SCLK_T: J7.1 J11.20 | length 743.1
  Bottom Layer w10: J11.20@1837.01,2037.01 1887,2087 1887,2642 J7.1@1970,2725
SDI: J9.2 J10.2 R23.2 | length 1556.7
  Top Layer w10: R23.2@1670,1711.5 1670,1765 1700,1795 v2(2244.5,1795) ; J9.2@2000,2420 J10.2@2260,2420
  Bottom Layer w10: v2(2244.5,1795) 2290,1840.5 2290,2390 J10.2@2260,2420
SDI_M: J1.17 J10.1 | length 2783.1
  Top Layer w10: J1.17@1937.01,3837.01 1985,3789.02 1985,3665 2025,3625 2750,3625 2785,3590 v2(2885,3590) ; J10.1@2260,2520 2376,2636 v2(2885,2636)
  Bottom Layer w10: v2(2885,2636) 2845,2676 2845,3550 v2(2885,3590)
SDI_T: J9.1 J11.16 | length 557.1
  Bottom Layer w10: J9.1@2000,2520 2108,2412 2108,2223 2090,2205 2090,2090 J11.16@2037.01,2037.01
SDO: J4.2 J5.2 R62.2 | length 2210.4
  Top Layer w10: J4.2@2610,3100 J5.2@2770,3100
  Bottom Layer w10: R62.2@2015,1711.5 2230.5,1711.5 2299,1780 2630,1780 2805,1955 2805,3065 J5.2@2770,3100
SDO_M: J1.19 J4.1 | length 1262.9
  Top Layer w10: J1.19@1837.01,3837.01 1885,3789.02 1885,3653.08 2023.08,3515 2545,3515 v1(2610,3450)
  Bottom Layer w10: J4.1@2610,3200 v1(2610,3450)
SDO_T: J1.15 J5.1 | length 1365
  Top Layer w10: J1.15@2037.01,3837.01 2085,3789.02 2085,3680 2115,3650 2790,3650 v2(2805,3635)
  Bottom Layer w10: J5.1@2770,3200 2770,3600 v2(2805,3635)
TEMP: C2.2 J1.8 R1.2 | length 724.6
  Top Layer w10: J1.8@2437.01,3737.01 2501.02,3672.99 2857.01,3672.99 2876.5,3653.5 R1.2@3055,3653.5 C2.2@3055,3581.5
UC3.3V: C1.1 C6.1 C8.1 C11.2 C26.2 C30.1 C31.1 FB1.2 L4.2 R2.2 R5.2 R8.2 R18.2 R20.2 R22.1 R68.1 TP13.1 U1.1 U2.1 U5.1 U5.2 U5.16 U6.19 U7.6 | length 11423.4
  Top Layer w10: 275,1703.5 298.5,1703.5 315.5,1720.5 U5.16@360.5,1720.5 ; U5.2@410.15,1690.55 410.15,1641.35 C30.1@470,1581.5
  Top Layer w12: C26.2@1580,1648.5 1580,1615 1600.43,1594.57 U6.19@1600.43,1550.24
  Top Layer w20: R22.1@1780,1716.5 1823.5,1760 2230,1760 2310,1680 v1(2310,1255) 2235,1255 v1(2080,1100) ; U2.1@1904.13,2905 1960,2905 1975,2890 C11.2@2038.5,2890 2038.5,2858.5 v1(2067.01,2830) ; R8.2@2101.5,3070 v1(2154,3070) ; v1(3095,3375) 3175,3375 3289.16,3489.16 3289.16,3629.16 3323.5,3663.5 C1.1@3323.5,3715 3280,3715 3256.34,3691.34 U1.1@3227.4,3691.34 ; U7.6@3555,1459 v1(3555,1535)
  Top Layer w25: R18.2@148.5,1915 v1(148.5,1970) ; v1(1301.5,1451.5) L4.2@1355,1451.5 ; v1(1520,1630) 1538.5,1648.5 C26.2@1580,1648.5 ; v1(1725.5,1716.5) R22.1@1780,1716.5 ; R5.2@2101.5,3230 v1(2101.5,3282.5) 2201.5,3282.5 2270,3351 2899,3351 v1(2915,3335) 3055,3335 v1(3095,3375)
  Top Layer w30: R2.2@1285,3600 v1(1360,3600)
  Bottom Layer w20: R68.1@2080,1041.5 v1(2080,1100) ; v1(2310,1255) 2585,1530 3124,1530 3229,1425 3515,1425 3555,1465 v1(3555,1535) 3245,1535 3123,1657 3123,2223 3170,2270 3170,3136 3095,3211 v1(3095,3375)
  Bottom Layer w25: v1(375,1400) 670,1400 820,1250 1010,1250 1211.5,1451.5 v1(1301.5,1451.5) 1350,1500 1460,1500 1520,1560 v1(1520,1630) 1585,1630 1671.5,1716.5 v1(1725.5,1716.5) ; v1(2067.01,2830) 2067.01,2900.01 2154,2987 v1(2154,3070) 2127.75,3070 2101.5,3096.25 v1(2101.5,3282.5) ; TP13.1@2915,3096 v1(2915,3335)
  Bottom Layer w30: v1(148.5,1970) 275,1843.5 v1(275,1681) ; v1(1360,3600) 1841.92,3600 2101.5,3340.42 v1(2101.5,3282.5)
  other v1: 270,1400 275,1621 2900,2900 2960,3026
UCA1RXD: J1.5 R9.1 TP16.1 | length 1176.6
  Top Layer w10: R9.1@2101.5,2990 2157,2990 2177,2970 TP16.1@2240,2970
  Bottom Layer w10: TP16.1@2240,2970 2240,3066 2560,3386 2560,3655 2585,3680 2585,3789.02 J1.5@2537.01,3837.01
UCA1TXD: J1.7 TP12.1 U2.6 | length 1172.4
  Top Layer w10: U2.6@1904.13,3155 1980,3155 2020,3195 TP12.1@2280,3195
  Bottom Layer w10: TP12.1@2280,3195 2525,3440 2525,3620 2485,3660 2485,3789.02 J1.7@2437.01,3837.01
VCC/2: C38.2 C42.2 J13.2 J14.2 J19.1 R52.2 R56.1 R60.1 R69.1 U8.2 | length 2380.1
  Top Layer w25: J14.2@1370,800 1525,800 v1(1576,749) ; R52.2@1885,723.5 v1(1941.5,723.5) ; U8.2@2077.5,797.5 2077.5,842.5 2105,870 v1(2170,870) 2198.5,841.5 C38.2@2198.5,765 2198.5,723.5 2185,710 2135,710 2123.5,698.5 C42.2@2123.5,650 ; R56.1@2097.41,555 2097.41,572.91 2123,598.5 C42.2@2123,650
  Top Layer w35: J19.1@2055,160 2097.91,202.91 R60.1@2097.91,440 R56.1@2097.91,555
  Bottom Layer w25: v1(1576,749) 1682,855 1886,855 1941.5,799.5 v1(1941.5,723.5) 2035.5,723.5 2080,768 R69.1@2080,828.5 2128.5,828.5 v1(2170,870) 2170,905 2220,955 2340,955 2360,975 J13.2@2360,1025
VREF_PH: C39.2 C40.2 C41.2 J13.1 J15.1 J16.1 J17.1 J18.1 Q2.4 Q2.7 Q3.4 Q3.7 Q4.4 Q4.7 R53.1 R54.1 R55.1 R57.1 R58.1 R59.1 R71.2 U6.8 | length 6101.5
  Top Layer w10: v1(1735,1400) 1753.98,1381.02 U6.8@1753.98,1329.76
  Top Layer w15: v2(765,1080) 784.41,1060.59 Q2.4@803.68,1060.59 ; Q2.7@836.22,1060.59 v2(836.22,1102.2) ; v2(935,1080) 954.41,1060.59 Q3.4@973.68,1060.59 ; Q3.7@1006.22,1060.59 v2(1006.22,1102.2) ; v2(1300,1080) 1319.41,1060.59 Q4.4@1338.68,1060.59 ; v2(1355,1105) 1371.22,1088.78 Q4.7@1371.22,1060.59
  Top Layer w25: R53.1@597.91,555 597.91,572.91 623.5,598.5 C39.2@623.5,650 v1(568,650) 568,1048 600,1080 v2(765,1080) ; v1(1068,650) C40.2@1120,650 ; R54.1@1094.41,556.5 1094.41,569.41 R54.1@1097.91,572.91 ; R54.1@1097.91,555 R54.1@1097.91,572.91 ; C40.2@1120,651.5 C40.2@1120,650 ; v1(1568,650) C41.2@1623.5,650 1623.5,598.5 1597.91,572.91 R55.1@1597.91,555 ; R54.1@1097.91,572.91 1123.5,598.5 C40.2@1123.5,650 C40.2@1120,650
  Top Layer w30: v1(1980,1025) J13.1@2260,1025 J15.1@2260,885
  Top Layer w35: J16.1@555,160 597.91,202.91 R57.1@597.91,440 R53.1@597.91,555 ; J17.1@1055,160 1097.91,202.91 R58.1@1097.91,440 R54.1@1097.91,555 ; J18.1@1555,160 1597.91,202.91 R59.1@1597.91,440 R55.1@1597.91,555
  Bottom Layer w15: v2(765,1080) 787.2,1102.2 v2(836.22,1102.2) 858.43,1080 v2(935,1080) 957.2,1102.2 v2(1006.22,1102.2) 1028.43,1080 v2(1300,1080) 1330,1080 v2(1355,1105)
  Bottom Layer w25: v1(568,650) v1(1068,650) v1(1568,650) ; v2(1355,1105) 1355,1225.45 1454.55,1325 1704.55,1325 1735,1355.45 v1(1735,1400) 1898.5,1400 1980,1318.5 v1(1980,1025)
  Bottom Layer w30: R71.2@1585,1451.5 1683.5,1451.5 v1(1735,1400)
Y_G: J11.10 R39.1 | length 1803.1
  Top Layer w10: R39.1@1025,1276.5 v1(1025,1340) ; v2(1760,1840) 1800,1880 2257.01,1880 2337.01,1960 J11.10@2337.01,2037.01
  Bottom Layer w10: v1(1025,1340) 1025,1500 1220,1695 1485,1695 1630,1840 v2(1760,1840)
Y_IP: C40.1 J17.2 R43.1 R49.1 R54.2 R58.2 TP32.1 | length 1516.2
  Top Layer w10: v2(1745,1095) R43.1@1745,1158.5
  Top Layer w25: TP32.1@1185,750 R49.1@1185,872.91 R49.1@1185,882.91 ; TP32.1@1186.5,748.5 C40.1@1186.5,650 1186.5,593.5 R54.2@1212.09,567.91
  Top Layer w35: R54.2@1212.09,567.91 R54.2@1212.09,555 R58.2@1212.09,440 1212.09,202.91 J17.2@1255,160
  Bottom Layer w10: TP32.1@1185,750 1400,750 v2(1745,1095)
pads on no net: D12.2 FID1.1 FID2.1 FID3.1 FID4.1 FID5.1 FID6.1 H1.1 H2.1 H3.1 H4.1 H7.1 HS1.1 HS1.2 T1.2 T1.5 U2.10 U2.11 U2.14

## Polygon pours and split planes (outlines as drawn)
GND on Top Layer "Top Layer-No Net 1" (hatched 90Degree grid 5 track 8, remove dead copper, pour order 44): 895,1335 895,1365 910,1380 1050,1380 1065,1365 1065,1150 1085,1130 1240,1130 1250,1140 1250,1236 1240,1246 1140,1246 1125,1261 1125,1445 1105,1465 930,1465 840,1375 840,1335 845,1330 890,1330
GND on Top Layer "Top Layer-No Net 1" (hatched 90Degree grid 5 track 8, remove dead copper, pour order 84): 1971.64,3270 1940,3300 1940,3383.83 2016.17,3460 2120,3460 2145,3435 2145,3390 2115,3360 2050,3360 2005,3315 2005,3275 2000,3270
GND on Top Layer "Top Layer-No Net 1" (hatched 90Degree grid 5 track 8, remove dead copper, pour order 83): 1025,3850 1515,3850 1685,3680 1840,3680 1855,3665 1855,3630 1845,3620 1495,3620 1355,3760 1025,3760 1005,3780 1005,3830
12V on Top Layer "Top Layer-No Net 2" (hatched 90Degree grid 5 track 8, remove dead copper, pour order 49): 310,1060 445,925 510,925 520,915 520,765 490,735 95,735 70,760 70,1040 90,1060
GND on Top Layer "Bottom Layer-No Net" (hatched 90Degree grid 5 track 8, remove dead copper, pour order 75): 95,1395 80,1410 80,1855 90,1865 155,1865 155,1775 135,1755 135,1605 175,1565 175,1405 165,1395
UC3.3V on Top Layer "Bottom Layer-No Net" (hatched 90Degree grid 5 track 8, remove dead copper, pour order 74): 425,1560 415,1550 415,1380 395,1360 245,1360 230,1375 230,1585 180,1635 180,1700 190,1710 305,1710 315,1720 370,1720 370,1695 405,1695 405,1640 430,1615 485,1615 495,1605 495,1565 490,1560
GND on Top Layer "Bottom Layer-No Net" (hatched 90Degree grid 5 track 8, remove dead copper, pour order 73): 470,1415 455,1430 455,1520 465,1530 500,1530 510,1540 510,1620 450,1680 429.85,1680.15 429.85,1690.55 430,1725 420,1735 420,1760 440,1760 440,1730 445,1725 505,1725 509.95,1719.85 535,1705 535,1609.67 560,1585 560,1475 570,1465 715,1465 720,1460 720,1420 715,1415
GND on Top Layer "Bottom Layer-No Net" (hatched 90Degree grid 5 track 8, remove dead copper, pour order 80): 745,1555 730,1570 665,1570 660,1575 660,1830 660,1865 670,1875 725,1875 735,1865 735,1840 735,1645 860,1645 870,1635 870,1570 855,1555
NetD11_2 on Top Layer "Top Layer-No Net 2" (hatched 90Degree grid 5 track 8, remove dead copper, pour order 54): 625,1284.55 605,1300 100.14,1300 85,1288.41 85,1160.91 125.37,1130 614.91,1130 625,1137.73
